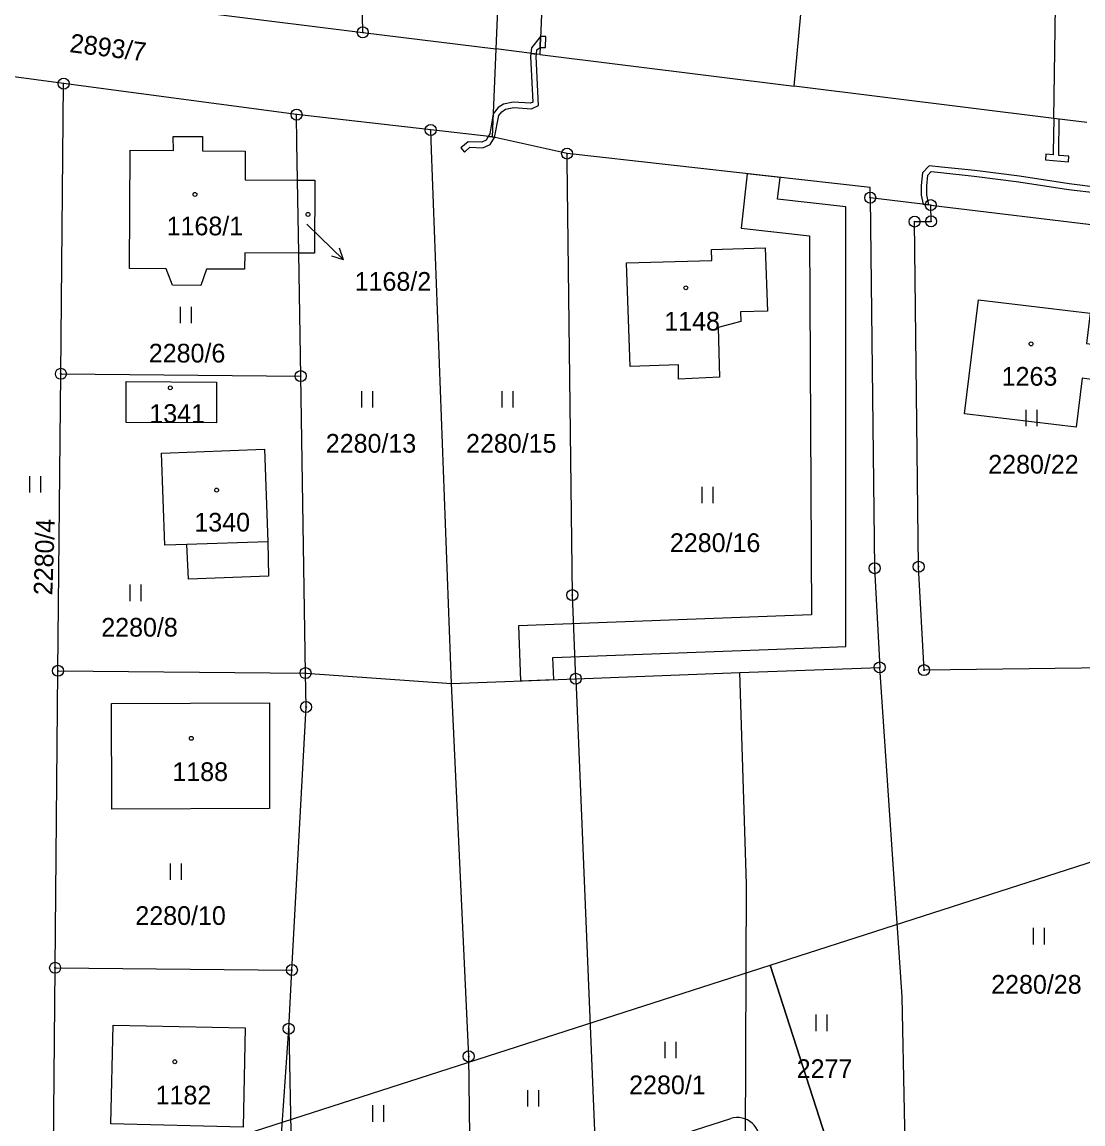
# Model space of a CAD drawing. Extents: x -758836 to -757729, y -1175316 to -1174366.
# Drawn here: x -758385.6 to -758289.2, y -1174737.5 to -1174637.3 of the extents above; entities that cross this region are included whole.
import ezdxf

# ---------------------------------------------------------------- set-up
doc = ezdxf.new("R2010")
doc.units = 0
for name, color, linetype in [('_NOR-pomocná', 7, 'Continuous'), ('_NOR-popis', 7, 'Continuous'), ('Hranice parcel', 7, 'Continuous'), ('Parcelní čísla', 7, 'Continuous'), ('Pop  PČ popisy', 7, 'Continuous'), ('Vnitřní kresba', 7, 'Continuous'), ('Věcná břemena k části', 7, 'Continuous'), ('Značky bodu BP', 7, 'Continuous'), ('Značky budov', 7, 'Continuous'), ('Značky kultur', 7, 'Continuous')]:
    doc.layers.add(name, color=color, linetype=linetype)

msp = doc.modelspace()

# ---------------------------------------------------------------- linework, layer by layer
at = {"layer": '_NOR-pomocná'}
for points in [[(-758317.65, -1174723.03), (-758217.71, -1174690.84), (-758172.18, -1174832.19), (-758272.12, -1174864.38)], [(-758417.59, -1174755.22), (-758317.65, -1174723.03), (-758272.12, -1174864.38), (-758372.07, -1174896.57)]]:
    msp.add_lwpolyline(points, close=True, dxfattribs=at)
at = {"layer": '_NOR-popis'}
msp.add_lwpolyline([(-758339.33, -1174742.8), (-758321.24, -1174736.98)], dxfattribs=at)
msp.add_arc((-758320.63, -1174738.88), 2, 287.8533, 107.854, dxfattribs=at)
at = {"layer": 'Hranice parcel'}
for p, q in [((-758354.67, -1174638.23), (-758355.96, -1174575.06)), ((-758367.77, -1174636.6), (-758354.67, -1174638.23)), ((-758354.67, -1174638.23), (-758342.58, -1174639.74)), ((-758338.6, -1174640.24), (-758342.58, -1174639.74)), ((-758338.6, -1174640.24), (-758315.47, -1174643.12)), ((-758381.85, -1174642.89), (-758386.84, -1174642.22)), ((-758382.1, -1174669.27), (-758381.85, -1174642.89)), ((-758360.69, -1174645.71), (-758381.85, -1174642.89)), ((-758291.89, -1174646.05), (-758315.47, -1174643.12)), ((-758348.5, -1174647.1), (-758360.69, -1174645.71)), ((-758288.89, -1174646.43), (-758291.89, -1174646.05)), ((-758342.92, -1174647.74), (-758348.5, -1174647.1)), ((-758336.11, -1174649.25), (-758342.92, -1174647.74)), ((-758360.49, -1174658.29), (-758360.6, -1174651.67)), ((-758303.07, -1174653.93), (-758308.57, -1174653.26)), ((-758303.07, -1174653.93), (-758282.56, -1174656.41)), ((-758360.31, -1174669.48), (-758360.49, -1174658.29)), ((-758382.36, -1174696.27), (-758382.1, -1174669.27)), ((-758382.1, -1174669.27), (-758360.31, -1174669.48)), ((-758359.87, -1174696.48), (-758360.31, -1174669.48)), ((-758382.62, -1174723.27), (-758382.36, -1174696.27)), ((-758382.36, -1174696.27), (-758359.87, -1174696.48)), ((-758359.87, -1174696.48), (-758346.61, -1174697.42)), ((-758335.32, -1174696.99), (-758320.43, -1174696.43)), ((-758320.43, -1174696.43), (-758307.71, -1174695.96)), ((-758346.61, -1174697.42), (-758335.32, -1174696.99)), ((-758382.9, -1174751.98), (-758382.62, -1174723.27)), ((-758382.62, -1174723.27), (-758361.11, -1174723.47)), ((-758361.4, -1174728.81), (-758361.11, -1174723.47)), ((-758363.13, -1174753.8), (-758361.4, -1174728.81)), ((-758361.4, -1174728.81), (-758361.02, -1174747.72))]:
    msp.add_line(p, q, dxfattribs=at)
for points in [[(-758342.95, -1174567.54), (-758341.45, -1174604.05), (-758341.43, -1174612.48), (-758342.58, -1174639.74)], [(-758314.25, -1174595.96), (-758337.67, -1174593.66), (-758337.43, -1174612.55), (-758338.6, -1174640.24)], [(-758315.47, -1174643.12), (-758313.89, -1174626.1), (-758314.16, -1174610.46)], [(-758291.89, -1174646.05), (-758291.43, -1174615.38), (-758291.45, -1174610.38)], [(-758342.58, -1174639.74), (-758342.77, -1174644.13), (-758342.92, -1174647.74)], [(-758360.6, -1174651.67), (-758360.65, -1174648.31), (-758360.69, -1174645.71)], [(-758360.49, -1174658.29), (-758365.4, -1174658.26), (-758365.41, -1174659.77), (-758368.86, -1174659.75), (-758369.38, -1174661.24), (-758371.96, -1174661.21), (-758372.54, -1174659.73), (-758375.85, -1174659.7), (-758375.81, -1174648.94), (-758371.88, -1174648.98), (-758371.89, -1174647.69), (-758369.24, -1174647.7), (-758369.24, -1174649), (-758365.35, -1174649.03), (-758365.37, -1174651.63), (-758360.6, -1174651.67)], [(-758346.61, -1174697.42), (-758348.43, -1174648.94), (-758348.5, -1174647.1)], [(-758335.32, -1174696.99), (-758335.63, -1174689.39), (-758336.1, -1174649.9), (-758336.11, -1174649.25)], [(-758308.57, -1174653.26), (-758308.58, -1174652.32), (-758336.11, -1174649.25)], [(-758360.6, -1174651.67), (-758359.03, -1174651.68), (-758359.07, -1174658.3), (-758360.49, -1174658.29)], [(-758308.57, -1174653.26), (-758308.17, -1174686.94), (-758307.71, -1174695.96)], [(-758282.22, -1174695.95), (-758303.68, -1174696.21), (-758304.17, -1174686.81), (-758304.54, -1174655.43), (-758303.04, -1174655.41), (-758303.07, -1174653.93)], [(-758326, -1174668.45), (-758330.39, -1174668.59), (-758330.71, -1174659.18), (-758322.96, -1174658.96), (-758322.99, -1174657.98), (-758318.1, -1174657.83), (-758317.91, -1174663.57), (-758320.35, -1174663.62), (-758320.32, -1174664.52), (-758322.37, -1174665.07), (-758322.25, -1174669.56), (-758325.98, -1174669.75), (-758326, -1174668.45)], [(-758298.73, -1174662.53), (-758288.59, -1174663.75), (-758288.93, -1174666.52), (-758286.98, -1174666.77), (-758287.37, -1174669.93), (-758289.32, -1174669.66), (-758289.87, -1174674.12), (-758300.02, -1174672.9), (-758298.73, -1174662.53)], [(-758376.18, -1174673.69), (-758376.17, -1174669.97), (-758367.96, -1174670.04), (-758367.96, -1174673.74), (-758376.18, -1174673.69)], [(-758363.59, -1174676.12), (-758363.3, -1174684.53), (-758363.25, -1174687.66), (-758370.5, -1174687.93), (-758370.66, -1174684.8), (-758372.66, -1174684.86), (-758372.97, -1174676.48), (-758363.59, -1174676.12)], [(-758361.11, -1174723.47), (-758359.82, -1174699.56), (-758359.87, -1174696.48)], [(-758319.98, -1174762.15), (-758319.82, -1174715.66), (-758320.43, -1174696.43)], [(-758305.02, -1174756.99), (-758305.68, -1174725.91), (-758307.71, -1174695.96)], [(-758344.78, -1174750.56), (-758345.05, -1174731.32), (-758346.61, -1174697.42)], [(-758335.32, -1174696.99), (-758333.07, -1174751.31), (-758333.29, -1174766.74)], [(-758363.16, -1174699.19), (-758363.15, -1174708.8), (-758377.47, -1174708.85), (-758377.5, -1174699.23), (-758363.16, -1174699.19)], [(-758377.57, -1174737.45), (-758377.35, -1174728.49), (-758365.35, -1174728.74), (-758365.55, -1174737.75), (-758377.57, -1174737.45)]]:
    msp.add_lwpolyline(points, dxfattribs=at)
at = {"layer": 'Pop  PČ popisy'}
for p, q in [((-758359.76, -1174655.66), (-758358.57, -1174656.81)), ((-758358.57, -1174656.81), (-758356.41, -1174658.9)), ((-758356.41, -1174658.9), (-758357.48, -1174658.56)), ((-758356.41, -1174658.9), (-758356.78, -1174657.84))]:
    msp.add_line(p, q, dxfattribs=at)
at = {"layer": 'Vnitřní kresba'}
msp.add_line((-758363.3, -1174684.53), (-758370.66, -1174684.8), dxfattribs=at)
at = {"layer": 'Věcná břemena k části'}
for points in [[(-758338.85, -1174639.82), (-758338.57, -1174639.59), (-758338.53, -1174638.59), (-758339.33, -1174639.62), (-758339.39, -1174640.14), (-758338.89, -1174640.2)], [(-758338.03, -1174638.61), (-758338.53, -1174638.59), (-758338.57, -1174639.59), (-758338.07, -1174639.61)], [(-758339.39, -1174640.14), (-758339.42, -1174640.41), (-758339.22, -1174644.56), (-758339.44, -1174644.67), (-758341, -1174644.56), (-758341.9, -1174644.76), (-758342.37, -1174645.06), (-758342.83, -1174645.64), (-758343.14, -1174647.46), (-758343.27, -1174647.7), (-758342.92, -1174647.74), (-758342.69, -1174647.79), (-758342.32, -1174645.8), (-758342.03, -1174645.44), (-758341.7, -1174645.22), (-758340.96, -1174645.06), (-758339.34, -1174645.17), (-758338.7, -1174644.88), (-758338.92, -1174640.43), (-758338.89, -1174640.2)], [(-758290.56, -1174649.99), (-758290.52, -1174649.49), (-758291.45, -1174649.41), (-758291.44, -1174649.16), (-758291.39, -1174646.11), (-758291.89, -1174646.05), (-758291.94, -1174649.11), (-758291.96, -1174649.37), (-758292.62, -1174649.31), (-758292.66, -1174649.81)], [(-758344.93, -1174648.67), (-758343.77, -1174648.72), (-758343.1, -1174648.42), (-758342.69, -1174647.79), (-758342.92, -1174647.74), (-758343.27, -1174647.7), (-758343.46, -1174648.04), (-758343.87, -1174648.22), (-758345.11, -1174648.17), (-758345.76, -1174648.74), (-758345.43, -1174649.11)], [(-758340.52, -1174692.17), (-758340.33, -1174697.18), (-758337.32, -1174697.07), (-758337.4, -1174695.06), (-758313.78, -1174694.19), (-758310.78, -1174694.07), (-758310.79, -1174654.09), (-758316.98, -1174653.4), (-758316.76, -1174651.41), (-758319.74, -1174651.08), (-758320.3, -1174656.04), (-758314.1, -1174656.74), (-758313.89, -1174691.19)]]:
    msp.add_lwpolyline(points, close=True, dxfattribs=at)
msp.add_lwpolyline([(-758287.87, -1174652.33), (-758290.49, -1174652), (-758295.01, -1174651.31), (-758299.08, -1174650.79), (-758302.1, -1174650.48), (-758303.2, -1174650.35), (-758303.83, -1174651), (-758303.93, -1174652.16), (-758303.94, -1174653.03), (-758303.77, -1174653.84), (-758303.25, -1174653.9), (-758303.44, -1174652.99), (-758303.43, -1174652.18), (-758303.35, -1174651.22), (-758303.02, -1174650.87), (-758302.16, -1174650.98), (-758299.14, -1174651.29), (-758295.07, -1174651.81), (-758290.55, -1174652.5), (-758287.93, -1174652.83)], dxfattribs=at)
at = {"layer": 'Značky bodu BP'}
for centre, radius in [((-758354.67, -1174638.23), 0.5), ((-758354.67, -1174638.23), 0.0303), ((-758381.85, -1174642.89), 0.5), ((-758381.85, -1174642.89), 0.0303), ((-758360.69, -1174645.71), 0.5), ((-758360.69, -1174645.71), 0.0303), ((-758348.5, -1174647.1), 0.5), ((-758348.5, -1174647.1), 0.0303), ((-758336.11, -1174649.25), 0.5), ((-758336.11, -1174649.25), 0.0303), ((-758308.57, -1174653.26), 0.5), ((-758308.57, -1174653.26), 0.0303), ((-758303.07, -1174653.93), 0.5), ((-758303.07, -1174653.93), 0.0303), ((-758304.54, -1174655.43), 0.5), ((-758304.54, -1174655.43), 0.0303), ((-758303.04, -1174655.41), 0.5), ((-758303.04, -1174655.41), 0.0303), ((-758382.1, -1174669.27), 0.5), ((-758382.1, -1174669.27), 0.0303), ((-758360.31, -1174669.48), 0.5), ((-758360.31, -1174669.48), 0.0303), ((-758308.17, -1174686.94), 0.5), ((-758304.17, -1174686.81), 0.5), ((-758304.17, -1174686.81), 0.0303), ((-758308.17, -1174686.94), 0.0303), ((-758335.63, -1174689.39), 0.5), ((-758335.63, -1174689.39), 0.0303), ((-758382.36, -1174696.27), 0.5), ((-758307.71, -1174695.96), 0.5), ((-758303.68, -1174696.21), 0.5), ((-758382.36, -1174696.27), 0.0303), ((-758359.87, -1174696.48), 0.5), ((-758359.87, -1174696.48), 0.0303), ((-758335.32, -1174696.99), 0.5), ((-758307.71, -1174695.96), 0.0303), ((-758303.68, -1174696.21), 0.0303), ((-758335.32, -1174696.99), 0.0303), ((-758359.82, -1174699.56), 0.5), ((-758359.82, -1174699.56), 0.0303), ((-758382.62, -1174723.27), 0.5), ((-758382.62, -1174723.27), 0.0303), ((-758361.11, -1174723.47), 0.5), ((-758361.11, -1174723.47), 0.0303), ((-758361.4, -1174728.81), 0.5), ((-758361.4, -1174728.81), 0.0303), ((-758345.05, -1174731.32), 0.5), ((-758345.05, -1174731.32), 0.0303)]:
    msp.add_circle(centre, radius, dxfattribs=at)
at = {"layer": 'Značky budov'}
for centre in [(-758369.92, -1174652.96), (-758359.65, -1174654.78), (-758325.32, -1174661.45), (-758293.96, -1174666.55), (-758372.16, -1174670.54), (-758367.95, -1174679.84), (-758370.25, -1174702.41), (-758371.75, -1174731.81)]:
    msp.add_circle(centre, 0.175, dxfattribs=at)
at = {"layer": 'Značky kultur'}
for p, q in [((-758371.23, -1174664.67), (-758371.23, -1174663.17)), ((-758370.23, -1174664.67), (-758370.23, -1174663.17)), ((-758354.75, -1174672.34), (-758354.75, -1174670.84)), ((-758353.75, -1174672.34), (-758353.75, -1174670.84)), ((-758342.02, -1174672.34), (-758342.02, -1174670.84)), ((-758341.02, -1174672.34), (-758341.02, -1174670.84)), ((-758294.41, -1174674.03), (-758294.41, -1174672.53)), ((-758293.41, -1174674.03), (-758293.41, -1174672.53)), ((-758384.91, -1174680.06), (-758384.91, -1174678.56)), ((-758383.91, -1174680.06), (-758383.91, -1174678.56)), ((-758323.85, -1174681.03), (-758323.85, -1174679.53)), ((-758322.85, -1174681.03), (-758322.85, -1174679.53)), ((-758375.81, -1174689.93), (-758375.81, -1174688.43)), ((-758374.81, -1174689.93), (-758374.81, -1174688.43)), ((-758372.15, -1174715.28), (-758372.15, -1174713.78)), ((-758371.15, -1174715.28), (-758371.15, -1174713.78)), ((-758293.75, -1174721.14), (-758293.75, -1174719.64)), ((-758292.75, -1174721.14), (-758292.75, -1174719.64)), ((-758313.48, -1174729.02), (-758313.48, -1174727.52)), ((-758312.48, -1174729.02), (-758312.48, -1174727.52)), ((-758327.19, -1174731.49), (-758327.19, -1174729.99)), ((-758326.19, -1174731.49), (-758326.19, -1174729.99)), ((-758339.69, -1174735.88), (-758339.69, -1174734.38)), ((-758338.69, -1174735.88), (-758338.69, -1174734.38)), ((-758353.75, -1174737.26), (-758353.75, -1174735.76)), ((-758352.75, -1174737.26), (-758352.75, -1174735.76))]:
    msp.add_line(p, q, dxfattribs=at)

# ---------------------------------------------------------------- texts
at = {"layer": 'Parcelní čísla'}
for s, rotation, p in [('2893/7', 353, (-758381.36, -1174640.02)), ('2280/4', 88, (-758382.88, -1174689.42))]:
    msp.add_text(s, height=1.7, rotation=rotation, dxfattribs=at).set_placement(p)
for s, p in [('1168/1', (-758372.49, -1174656.68)), ('1168/2', (-758355.41, -1174661.72)), ('1148', (-758327.28, -1174665.34)), ('2280/6', (-758374.11, -1174668.24)), ('1263', (-758296.63, -1174670.35)), ('1341', (-758374.06, -1174673.73)), ('2280/13', (-758358.03, -1174676.44)), ('2280/15', (-758345.29, -1174676.44)), ('2280/22', (-758297.85, -1174678.34)), ('1340', (-758369.97, -1174683.61)), ('2280/16', (-758326.77, -1174685.47)), ('2280/8', (-758378.43, -1174693.16)), ('1188', (-758371.97, -1174706.29)), ('2280/10', (-758375.33, -1174719.37)), ('2280/28', (-758297.58, -1174725.62)), ('2277', (-758315.25, -1174733.29)), ('2280/1', (-758330.47, -1174734.76)), ('1182', (-758373.49, -1174735.69))]:
    msp.add_text(s, height=1.7, dxfattribs=at).set_placement(p)

doc.saveas('drawing.dxf')
